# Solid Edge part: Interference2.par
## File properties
Last saved by: Cadcim
Revision: 44
Accuracy: 0.99
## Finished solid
Body 1: solid body, 6 faces, 6 edges, 0 vertices.
  Faces by surface: cylinder 3, cone 2, plane 1
  Edges by curve: circle 4, intersection 2
Body 2: solid body, 6 faces, 6 edges, 0 vertices.
  Faces by surface: cylinder 3, cone 2, plane 1
  Edges by curve: circle 4, intersection 2
Body 3: solid body, 6 faces, 6 edges, 0 vertices.
  Faces by surface: cylinder 3, cone 2, plane 1
  Edges by curve: circle 4, intersection 2
Body 4: solid body, 6 faces, 6 edges, 0 vertices.
  Faces by surface: cylinder 3, cone 2, plane 1
  Edges by curve: circle 4, intersection 2
Bounding box of the edges (mm): 152.400 x 152.400 x 25.400, from (-76.2, -76.2, 70.5218) to (76.2, 76.2, 95.9218).
Cylindrical faces by radius (mm): R9.5123 x4, R12.7 x4, R76.2 x4
Conical faces (half-angle, radius in mm at the cone's reference point): 45 deg R12.7 x4, 59 deg R9.5123 x4
Planar faces by outward normal: +x 1, +y 1, -x 1, -y 1
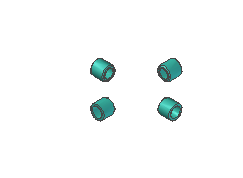
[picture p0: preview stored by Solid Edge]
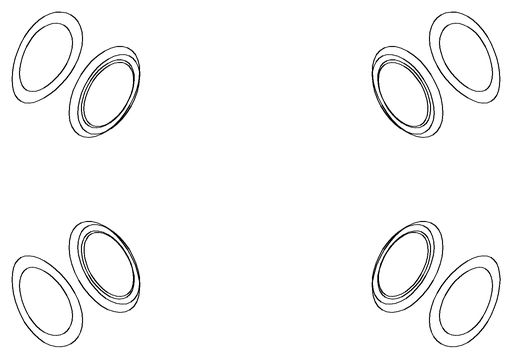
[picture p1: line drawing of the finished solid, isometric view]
